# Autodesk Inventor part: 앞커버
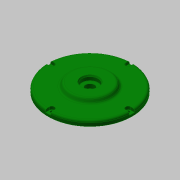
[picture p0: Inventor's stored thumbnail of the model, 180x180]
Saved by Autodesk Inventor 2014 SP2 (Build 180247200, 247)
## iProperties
Created: 2016-11
Part Number: 앞커버
Material: 일반
Document SubType Name: Modeling
Designer: mduedu
Density: 1 g/cm^3
Mass: 145.694 g
Surface Area: 366.671 cm^2
Volume: 145.694 cm^3
Appearance: 진녹색
Author: mduedu
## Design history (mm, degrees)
sketch "스케치1"
  geometry: L1 (22, -12.5)-(22, -30); L2 (22, -30)-(16, -33.464); L3 (16, -33.464)-(16, -65); L4 (16, -65)-(8, -65); L5 (8, -65)-(8, -53); L6 (8, -53)-(0, -53); L7 (0, -53)-(0, -14); L8 (0, 0)-(22, 0); L9 (8, -14)-(8, -7); L10 (8, -7)-(14.5, -7); L11 (14.5, -7)-(14.5, -12.5); L12 (0, -14)-(8, -14); L13 (14.5, -12.5)-(22, -12.5)
  constraints: 26 end point, 8 parallel, 3 perpendicular, 2 horizontal, 2 vertical alignment, 1 collinear
  dimensions: "d0" = 8 distance of L5.end L6.end; "d2" = 8 distance of L3.end L4.end; "d3" = 6 distance between parallel lines of L1 L3; "d4" = 120 deg angle of L3 L2; "d5" = 7.5 distance of L11.end L1.start; "d6" = 60 diameter of L1.end L8; "d7" = 14 diameter of L10 L8; "d8" = 28 diameter of L12 L8; "d9" = 25 diameter of L13 L8; "d10" = 106 diameter of L6 L8; "d11" = 130 diameter of L4 L8
revolve "회전1" sketch "스케치1" stored, may be unused: angle "d12" = 90 deg
fillet "모깎기1" dims "d13" = 0.3
fillet "모깎기2" dims "d14" = 3
chamfer "모따기1" distance "d15" = 1; stored, may be unused: second distance "d16" = 2, angle "d17" = 45 deg
fillet "모깎기3" dims "d18" = 0.3
chamfer "모따기2" distance "d36" = 2; stored, may be unused: second distance "d37" = 2, angle "d38" = 30 deg
sketch "스케치3"
  geometry: C1 r 65 at (0, 0) reference; A1 r 59 centre (0, 0) between (0, 59) and (59, 0); 2 further points
  constraints: 4 point on circle, 2 horizontal alignment, 2 vertical alignment, 1 centre point, 1 coincident
  dimensions: "d33" = 118 diameter of A1
sketch "스케치4"
  geometry: 4 further points
  constraints: 4 other
hole "구멍2" sketch "스케치4" at (0, 59), (-59, 0), (59, 0), (0, -59) diameter "d39" = 4.5; stored, may be unused: countersink angle "d43" = 90 deg, drill point angle "d45" = 0 deg; dims "d40" = 6, "d41" = 8, "d42" = 4.6, "d44" = 8
sketch "스케치6"
  geometry: L1 (-4, 5.877)-(-4, 0); L2 (4, 5.877)-(4, 0); A1 r 4 centre (0, 0) between (-2.712, 2.941) and (2.712, 2.941) reference; A2 r 65 centre (0, -59) between (-4, 5.877) and (4, 5.877) reference; 1 further point
  constraints: 4 end point, 4 point on circle, 2 tangent, 2 vertical
extrude "돌출2" cut sketch "스케치6" stored distance "d51" = 10; taper "d52" = 0 deg
sketch "스케치5"
  geometry: C1 r 22 at (0, 0); C2 r 45 at (0, 0); 1 further point
  constraints: 2 centre point, 2 coincident
  dimensions: "d46" = 44 diameter of C1; "d47" = 90 diameter of C2
extrude "돌출1" cut sketch "스케치5" distance "d48" = 8; taper "d49" = 0 deg
fillet "모깎기4" dims "d50" = 3
node "솔리드1"
pattern_circular "원형 패턴1" dims angle "d54" = 360 deg
